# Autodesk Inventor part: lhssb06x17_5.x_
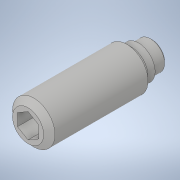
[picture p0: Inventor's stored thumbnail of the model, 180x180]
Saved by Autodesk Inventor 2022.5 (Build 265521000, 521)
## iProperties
Created: 2021-02
Part Number: lhssb06x17_5.x_
Material: 一般
Document SubType Name: Modeling
Designer: ImaoCorp
Density: 1 g/cm^3
Appearance: 既定
Sending System: SOLIDWORKS 2019-2019304
MC: AMD64
MC_MODEL: Intel64 Family 6 Model 60 Stepping 3, GenuineIntel
OS: Windows_NT
FRU: Parasolid Version 31.0, build 290,  9- 1-2019
FORMAT: text
GUISE: transmit
KEY: lhssb06x17_5
FILE: lhssb06x17_5.x_t
DATE: Mon Feb 22 14:56:12 2021
Author: ImaoCorp
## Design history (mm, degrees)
feature "Base1"
node "ソリッド1"
